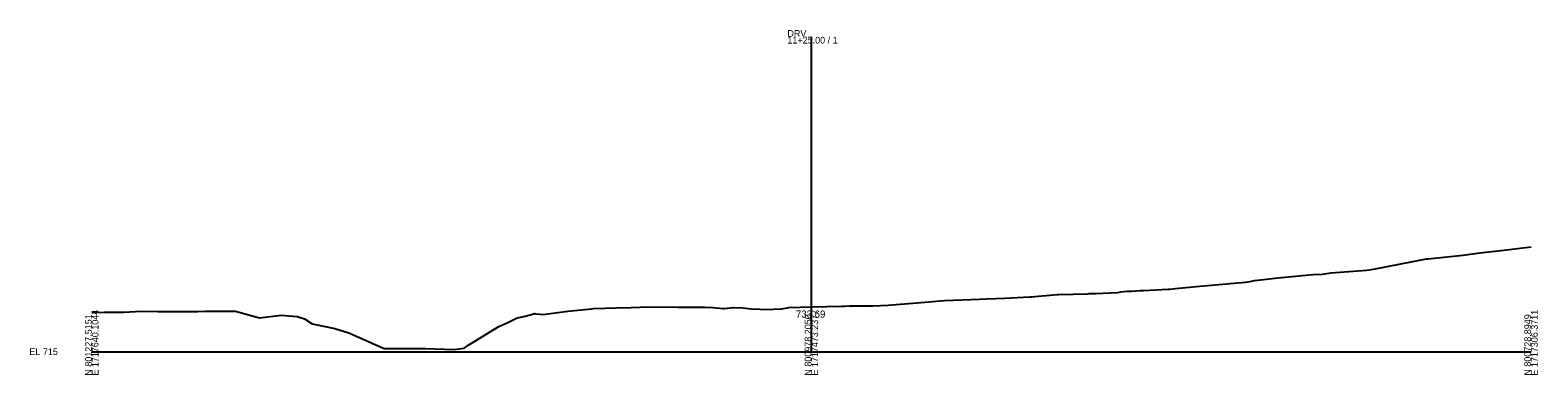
# Model space of a CAD drawing. Extents: x -26 to 603, y -10 to 3134.
# Drawn here: x -26 to 603, y 2990 to 3134 of the extents above; entities that cross this region are included whole.
import ezdxf

# ---------------------------------------------------------------- set-up
doc = ezdxf.new("R2010")
doc.units = 0
for name, color, linetype in [('Exist Cross Section Cell', 7, 'Continuous'), ('Exist XS Center Line Elevation Label', 7, 'Continuous'), ('Exist XS Ground Line', 7, 'Continuous'), ('Prop XS Finish Grade Earthwork', 7, 'Continuous')]:
    doc.layers.add(name, color=color, linetype=linetype)

msp = doc.modelspace()

# ---------------------------------------------------------------- linework, layer by layer
at = {"layer": 'Exist Cross Section Cell'}
for p, q in [((300, 3000), (300, 3131.45)), ((0, 3000), (300, 3000)), ((300, 3000), (600, 3000))]:
    msp.add_line(p, q, dxfattribs=at)
at = {"layer": 'Exist XS Ground Line'}
for p, q in [((578.64, 3041.22), (589.92, 3042.58)), ((589.92, 3042.58), (594.39, 3043.13)), ((594.39, 3043.13), (600, 3043.82)), ((534.38, 3034.51), (556.4, 3038.71)), ((556.4, 3038.71), (556.71, 3038.75)), ((556.71, 3038.75), (557.02, 3038.78)), ((557.02, 3038.78), (571.65, 3040.35)), ((571.65, 3040.35), (578.64, 3041.22)), ((482.93, 3029.33), (484.66, 3029.69)), ((484.66, 3029.69), (494.62, 3030.8)), ((494.62, 3030.8), (508.97, 3032.17)), ((508.97, 3032.17), (513.01, 3032.37)), ((513.01, 3032.37), (516.57, 3032.86)), ((516.57, 3032.86), (531.6, 3033.96)), ((531.6, 3033.96), (534.38, 3034.51)), ((391.59, 3022.92), (402.45, 3023.85)), ((402.45, 3023.85), (402.96, 3023.87)), ((402.96, 3023.87), (415.19, 3024.21)), ((415.19, 3024.21), (415.85, 3024.28)), ((415.85, 3024.28), (418.54, 3024.31)), ((418.54, 3024.31), (427.69, 3024.7)), ((427.69, 3024.7), (428.93, 3024.96)), ((428.93, 3024.96), (431.63, 3025.29)), ((431.63, 3025.29), (433.38, 3025.33)), ((433.38, 3025.33), (437, 3025.54)), ((437, 3025.54), (437.52, 3025.51)), ((437.52, 3025.51), (438.5, 3025.54)), ((438.5, 3025.54), (448.69, 3026.05)), ((448.69, 3026.05), (449.43, 3026.13)), ((449.43, 3026.13), (451.73, 3026.37)), ((451.73, 3026.37), (458.96, 3027.01)), ((458.96, 3027.01), (460.35, 3027.19)), ((460.35, 3027.19), (480.93, 3029.04)), ((480.93, 3029.04), (482.93, 3029.33)), ((198.39, 3016.91), (206.92, 3017.7)), ((206.92, 3017.7), (208.5, 3017.87)), ((208.5, 3017.87), (209.18, 3017.96)), ((209.18, 3017.96), (218.59, 3018.28)), ((218.59, 3018.28), (224.83, 3018.5)), ((224.83, 3018.5), (228.45, 3018.64)), ((228.45, 3018.64), (230.82, 3018.74)), ((230.82, 3018.74), (244.39, 3018.62)), ((244.39, 3018.62), (246.54, 3018.58)), ((246.54, 3018.58), (248.88, 3018.56)), ((248.88, 3018.56), (255.5, 3018.54)), ((255.5, 3018.54), (255.53, 3018.53)), ((255.53, 3018.53), (258.87, 3018.43)), ((258.87, 3018.43), (263.28, 3018.01)), ((263.28, 3018.01), (263.55, 3018)), ((263.55, 3018), (263.64, 3017.99)), ((263.64, 3017.99), (267.43, 3018.38)), ((267.43, 3018.38), (267.75, 3018.38)), ((267.75, 3018.38), (271.4, 3018.31)), ((271.4, 3018.31), (275.97, 3017.74)), ((275.97, 3017.74), (276.88, 3017.85)), ((276.88, 3017.85), (280.45, 3017.6)), ((280.45, 3017.6), (287.72, 3017.89)), ((287.72, 3017.89), (290.62, 3018.43)), ((290.62, 3018.43), (300, 3018.69)), ((300, 3018.69), (312.53, 3019.03)), ((312.53, 3019.03), (313.98, 3019.05)), ((313.98, 3019.05), (315.99, 3019.09)), ((315.99, 3019.09), (323.67, 3019.19)), ((323.67, 3019.19), (325.57, 3019.19)), ((325.57, 3019.19), (332.06, 3019.42)), ((332.06, 3019.42), (336.94, 3019.88)), ((336.94, 3019.88), (342.25, 3020.32)), ((342.25, 3020.32), (355.55, 3021.33)), ((355.55, 3021.33), (370.11, 3021.86)), ((370.11, 3021.86), (373.02, 3022.01)), ((373.02, 3022.01), (380.58, 3022.38)), ((380.58, 3022.38), (391.04, 3022.85)), ((391.04, 3022.85), (391.59, 3022.92)), ((0, 3016.32), (0.76, 3016.29)), ((0.76, 3016.29), (5.11, 3016.56)), ((5.11, 3016.56), (13.19, 3016.47)), ((13.19, 3016.47), (20.71, 3016.9)), ((20.71, 3016.9), (27.49, 3016.73)), ((27.49, 3016.73), (30.35, 3016.79)), ((30.35, 3016.79), (34.21, 3016.75)), ((34.21, 3016.75), (44.24, 3016.79)), ((44.24, 3016.79), (47.07, 3016.85)), ((47.07, 3016.85), (58.91, 3016.92)), ((58.91, 3016.92), (59.89, 3016.9)), ((59.89, 3016.9), (69.92, 3014.15)), ((69.92, 3014.15), (78.99, 3015.22)), ((78.99, 3015.22), (85.64, 3014.7)), ((85.64, 3014.7), (88.63, 3013.69)), ((88.63, 3013.69), (91.94, 3011.58)), ((91.94, 3011.58), (92.05, 3011.56)), ((92.05, 3011.56), (92.53, 3011.48)), ((92.53, 3011.48), (101.31, 3009.72)), ((169.37, 3010.31), (173.74, 3012.35)), ((173.74, 3012.35), (174.78, 3012.93)), ((174.78, 3012.93), (177.12, 3013.94)), ((177.12, 3013.94), (177.43, 3014.08)), ((177.43, 3014.08), (177.48, 3014.09)), ((177.48, 3014.09), (180.7, 3014.85)), ((180.7, 3014.85), (183.77, 3015.66)), ((183.77, 3015.66), (184.58, 3015.88)), ((184.58, 3015.88), (184.67, 3015.87)), ((184.67, 3015.87), (185.05, 3015.82)), ((185.05, 3015.82), (188.6, 3015.53)), ((188.6, 3015.53), (189.09, 3015.59)), ((189.09, 3015.59), (198.39, 3016.91)), ((101.31, 3009.72), (107.2, 3007.87)), ((107.2, 3007.87), (121.84, 3001.27)), ((157.17, 3002.86), (159.94, 3004.51)), ((159.94, 3004.51), (169.37, 3010.31)), ((121.84, 3001.27), (139.1, 3001.32)), ((139.1, 3001.32), (151.12, 3000.86)), ((151.12, 3000.86), (155.19, 3001.5)), ((155.19, 3001.5), (157.17, 3002.86))]:
    msp.add_line(p, q, dxfattribs=at)
at = {"layer": 'Prop XS Finish Grade Earthwork'}
msp.add_line((324.76, 3019.05), (325.1, 3019.19), dxfattribs=at)

# ---------------------------------------------------------------- texts
at = {"layer": 'Exist Cross Section Cell'}
for s, p in [('11+25.00 / 1', (290, 3128.65)), ('DRV', (290, 3131.45)), ('EL 715', (-26, 2998.6))]:
    msp.add_text(s, height=2.8, dxfattribs=at).set_placement(p)
for s, p in [('E 1717640.1044', (2.8, 2990)), ('E 1717473.2377', (302.8, 2990)), ('E 1717306.3711', (602.8, 2990)), ('N 801227.5151', (0, 2990)), ('N 800978.2050', (300, 2990)), ('N 800728.8949', (600, 2990))]:
    msp.add_text(s, height=2.8, rotation=90, dxfattribs=at).set_placement(p)
at = {"layer": 'Exist XS Center Line Elevation Label'}
msp.add_text('733.69', height=3, dxfattribs=at).set_placement((293.55, 3014.19))

doc.saveas('drawing.dxf')
